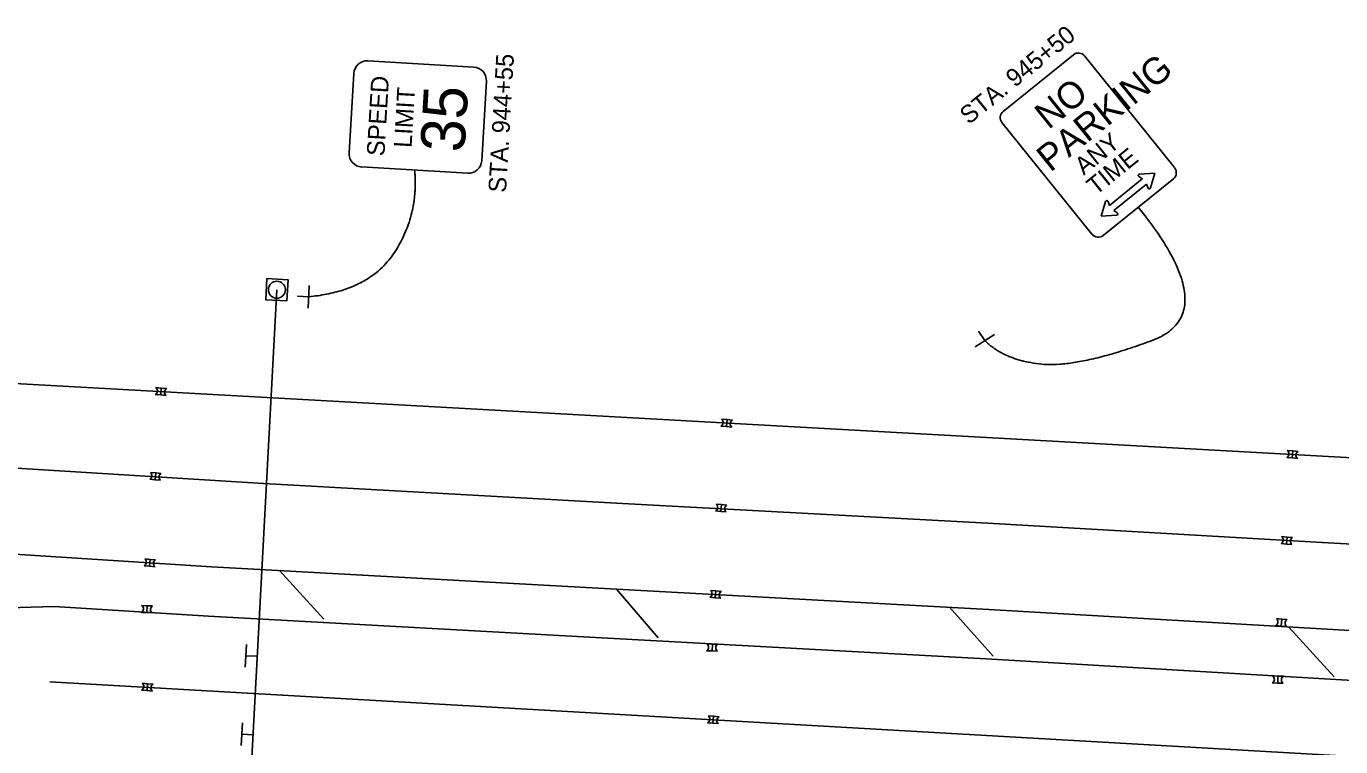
# Model space of a CAD drawing. Extents: x 1847379 to 1850904, y 217032 to 220169.
# Drawn here: x 1848555.2 to 1848740.8, y 218856.2 to 218957.9 of the extents above; entities that cross this region are included whole.
import ezdxf

# ---------------------------------------------------------------- set-up
doc = ezdxf.new("R2010")
doc.units = 0
for name, color, linetype in [('PM_P_Cells', 7, 'Continuous'), ('PM_P_CL_Double_Solid', 7, 'Continuous'), ('PM_P_Edge_Line', 7, 'Continuous'), ('PM_P_Lane_Line', 7, 'Continuous'), ('PM_P_Transverse_Line', 7, 'Continuous'), ('SG_P_Poles', 7, 'Continuous'), ('SN_P_Signs', 7, 'Continuous'), ('SN_X_Public', 7, 'Continuous')]:
    doc.layers.add(name, color=color, linetype=linetype)

msp = doc.modelspace()

# ---------------------------------------------------------------- linework, layer by layer
at = {"layer": 'PM_P_Cells'}
for p, q in [((1848574.25, 218906.8), (1848573.48, 218906.87)), ((1848573.48, 218906.87), (1848574.25, 218906.8)), ((1848574.16, 218905.83), (1848574.25, 218906.8)), ((1848574.25, 218906.8), (1848575.02, 218906.73)), ((1848573.39, 218905.9), (1848574.16, 218905.83)), ((1848573.39, 218905.9), (1848574.16, 218905.83)), ((1848574.16, 218905.83), (1848574.93, 218905.76)), ((1848654.13, 218902.35), (1848653.36, 218902.42)), ((1848653.36, 218902.42), (1848654.13, 218902.35)), ((1848653.27, 218901.45), (1848654.04, 218901.38)), ((1848653.27, 218901.45), (1848654.04, 218901.38)), ((1848654.04, 218901.38), (1848654.13, 218902.35)), ((1848654.04, 218901.38), (1848654.81, 218901.31)), ((1848654.13, 218902.35), (1848654.9, 218902.28)), ((1848733.16, 218897.02), (1848733.92, 218896.95)), ((1848733.16, 218897.02), (1848733.92, 218896.95)), ((1848734.01, 218897.93), (1848733.24, 218898)), ((1848733.24, 218898), (1848734.01, 218897.93)), ((1848733.92, 218896.95), (1848734.01, 218897.93)), ((1848733.92, 218896.95), (1848734.69, 218896.88)), ((1848734.01, 218897.93), (1848734.78, 218897.86)), ((1848572.62, 218893.93), (1848573.38, 218893.86)), ((1848572.62, 218893.93), (1848573.38, 218893.86)), ((1848573.47, 218894.83), (1848572.71, 218894.9)), ((1848572.71, 218894.9), (1848573.47, 218894.83)), ((1848573.38, 218893.86), (1848573.47, 218894.83)), ((1848573.38, 218893.86), (1848574.15, 218893.79)), ((1848573.47, 218894.83), (1848574.24, 218894.76)), ((1848652.5, 218889.46), (1848653.26, 218889.39)), ((1848652.5, 218889.46), (1848653.26, 218889.39)), ((1848653.35, 218890.36), (1848652.58, 218890.43)), ((1848652.58, 218890.43), (1848653.35, 218890.36)), ((1848653.26, 218889.39), (1848653.35, 218890.36)), ((1848653.26, 218889.39), (1848654.03, 218889.32)), ((1848653.35, 218890.36), (1848654.12, 218890.29)), ((1848733.22, 218885.77), (1848732.45, 218885.84)), ((1848732.45, 218885.84), (1848733.22, 218885.77)), ((1848733.13, 218884.79), (1848733.22, 218885.77)), ((1848733.22, 218885.77), (1848733.99, 218885.7)), ((1848732.37, 218884.86), (1848733.13, 218884.79)), ((1848732.37, 218884.86), (1848733.13, 218884.79)), ((1848733.13, 218884.79), (1848733.9, 218884.72)), ((1848572.68, 218882.63), (1848571.91, 218882.7)), ((1848571.91, 218882.7), (1848572.68, 218882.63)), ((1848572.59, 218881.66), (1848572.68, 218882.63)), ((1848572.68, 218882.63), (1848573.45, 218882.56)), ((1848571.82, 218881.73), (1848572.59, 218881.66)), ((1848571.82, 218881.73), (1848572.59, 218881.66)), ((1848572.59, 218881.66), (1848573.36, 218881.59)), ((1848652.56, 218878.18), (1848651.79, 218878.25)), ((1848651.79, 218878.25), (1848652.56, 218878.18)), ((1848651.7, 218877.28), (1848652.47, 218877.21)), ((1848651.7, 218877.28), (1848652.47, 218877.21)), ((1848652.47, 218877.21), (1848652.56, 218878.18)), ((1848652.47, 218877.21), (1848653.24, 218877.14)), ((1848652.56, 218878.18), (1848653.33, 218878.11)), ((1848571.43, 218875.14), (1848572.2, 218875.11)), ((1848571.43, 218875.14), (1848572.2, 218875.11)), ((1848572.24, 218876.09), (1848571.47, 218876.11)), ((1848571.47, 218876.11), (1848572.24, 218876.09)), ((1848572.2, 218875.11), (1848572.24, 218876.09)), ((1848572.2, 218875.11), (1848572.97, 218875.08)), ((1848572.24, 218876.09), (1848573.01, 218876.06)), ((1848731.61, 218873.29), (1848732.38, 218873.22)), ((1848731.61, 218873.29), (1848732.38, 218873.22)), ((1848732.47, 218874.19), (1848731.7, 218874.26)), ((1848731.7, 218874.26), (1848732.47, 218874.19)), ((1848732.38, 218873.22), (1848732.47, 218874.19)), ((1848732.38, 218873.22), (1848733.15, 218873.15)), ((1848732.47, 218874.19), (1848733.24, 218874.13)), ((1848651.25, 218869.73), (1848652.02, 218869.71)), ((1848651.25, 218869.73), (1848652.02, 218869.71)), ((1848652.06, 218870.68), (1848651.29, 218870.71)), ((1848651.29, 218870.71), (1848652.06, 218870.68)), ((1848652.02, 218869.71), (1848652.06, 218870.68)), ((1848652.02, 218869.71), (1848652.79, 218869.68)), ((1848652.06, 218870.68), (1848652.83, 218870.66)), ((1848731.93, 218866.15), (1848731.16, 218866.18)), ((1848731.16, 218866.18), (1848731.93, 218866.15)), ((1848731.9, 218865.17), (1848731.93, 218866.15)), ((1848731.93, 218866.15), (1848732.7, 218866.12)), ((1848571.46, 218864.17), (1848572.23, 218864.1)), ((1848571.46, 218864.17), (1848572.23, 218864.1)), ((1848572.32, 218865.08), (1848571.55, 218865.15)), ((1848571.55, 218865.15), (1848572.32, 218865.08)), ((1848572.23, 218864.1), (1848572.32, 218865.08)), ((1848572.23, 218864.1), (1848573, 218864.04)), ((1848572.32, 218865.08), (1848573.09, 218865.01)), ((1848731.13, 218865.2), (1848731.9, 218865.17)), ((1848731.13, 218865.2), (1848731.9, 218865.17)), ((1848731.9, 218865.17), (1848732.67, 218865.14)), ((1848652.23, 218860.48), (1848651.47, 218860.55)), ((1848651.47, 218860.55), (1848652.23, 218860.48)), ((1848652.15, 218859.5), (1848652.23, 218860.48)), ((1848652.23, 218860.48), (1848653, 218860.41)), ((1848651.38, 218859.57), (1848652.15, 218859.5)), ((1848651.38, 218859.57), (1848652.15, 218859.5)), ((1848652.15, 218859.5), (1848652.91, 218859.44))]:
    msp.add_line(p, q, dxfattribs=at)
for centre, start, end in [((1848573.13, 218906.41), 296.8063, 52.8586), ((1848573.13, 218906.41), 296.8063, 52.8586), ((1848575.28, 218906.22), 116.8063, 232.8586), ((1848653.01, 218901.96), 296.8063, 52.8586), ((1848653.01, 218901.96), 296.8063, 52.8586), ((1848655.16, 218901.77), 116.8063, 232.8586), ((1848732.9, 218897.54), 296.8063, 52.8586), ((1848732.9, 218897.54), 296.8063, 52.8586), ((1848735.04, 218897.34), 116.8063, 232.8586), ((1848572.36, 218894.44), 296.8063, 52.8586), ((1848572.36, 218894.44), 296.8063, 52.8586), ((1848574.5, 218894.25), 116.8063, 232.8586), ((1848652.24, 218889.97), 296.8063, 52.8586), ((1848652.24, 218889.97), 296.8063, 52.8586), ((1848654.38, 218889.78), 116.8063, 232.8586), ((1848732.11, 218885.38), 296.8063, 52.8586), ((1848732.11, 218885.38), 296.8063, 52.8586), ((1848734.25, 218885.18), 116.8063, 232.8586), ((1848571.56, 218882.24), 296.8063, 52.8586), ((1848571.56, 218882.24), 296.8063, 52.8586), ((1848573.71, 218882.05), 116.8063, 232.8586), ((1848651.44, 218877.79), 296.8063, 52.8586), ((1848651.44, 218877.79), 296.8063, 52.8586), ((1848653.59, 218877.6), 116.8063, 232.8586), ((1848571.15, 218875.64), 299.9028, 55.9551), ((1848571.15, 218875.64), 299.9028, 55.9551), ((1848573.3, 218875.56), 119.9028, 235.9551), ((1848731.35, 218873.81), 296.8063, 52.8586), ((1848731.35, 218873.81), 296.8063, 52.8586), ((1848733.5, 218873.61), 116.8063, 232.8586), ((1848650.96, 218870.23), 299.9028, 55.9551), ((1848650.96, 218870.23), 299.9028, 55.9551), ((1848653.11, 218870.16), 119.9028, 235.9551), ((1848730.84, 218865.7), 299.9028, 55.9551), ((1848730.84, 218865.7), 299.9028, 55.9551), ((1848732.99, 218865.62), 119.9028, 235.9551), ((1848571.2, 218864.69), 296.8063, 52.8586), ((1848571.2, 218864.69), 296.8063, 52.8586), ((1848573.35, 218864.49), 116.8063, 232.8586), ((1848651.12, 218860.09), 296.8063, 52.8586), ((1848651.12, 218860.09), 296.8063, 52.8586), ((1848653.26, 218859.89), 116.8063, 232.8586)]:
    msp.add_arc(centre, 0.576, start, end, dxfattribs=at)
at = {"layer": 'PM_P_CL_Double_Solid'}
msp.add_line((1848494.98, 218874.17), (1848559.13, 218875.98), dxfattribs=at)
for points in [[(1848092.4, 218893.94), (1848142.1, 218891.52), (1848192.74, 218889.17), (1848244.1, 218886.91), (1848292.7, 218884.63), (1848342.36, 218882.33), (1848384.68, 218880.9), (1848410.72, 218884.71), (1848435.62, 218888.6), (1848446.29, 218889.11), (1848496.28, 218886.67), (1848532.23, 218884.71), (1848581.34, 218881.58), (1848635.08, 218878.63), (1848691.11, 218875.57), (1848742.91, 218872.53), (1848797.97, 218869.41), (1848838.45, 218867.24), (1848839.96, 218866.49), (1848840.79, 218865.04), (1848840.57, 218862.3), (1848839.59, 218860.87), (1848837.82, 218860.26)], [(1848559.13, 218875.98), (1848580.93, 218874.59), (1848634.7, 218871.64), (1848690.71, 218868.59), (1848742.51, 218865.54), (1848797.58, 218862.42), (1848837.82, 218860.26)]]:
    msp.add_lwpolyline(points, dxfattribs=at)
at = {"layer": 'PM_P_Edge_Line'}
msp.add_line((1848468.87, 218912.17), (1848839.16, 218891.61), dxfattribs=at)
at = {"layer": 'PM_P_Lane_Line'}
msp.add_line((1848558.52, 218865.36), (1848836.12, 218849.43), dxfattribs=at)
msp.add_lwpolyline([(1848093.91, 218917.13), (1848143.09, 218915.12), (1848190.28, 218912.91), (1848241.04, 218910.6), (1848292.87, 218908.29), (1848342.88, 218905.97), (1848396.54, 218903.43), (1848443.56, 218901.44), (1848492.82, 218898.95), (1848543.12, 218896.17), (1848588.69, 218893.34), (1848639.37, 218890.51), (1848690.94, 218887.73), (1848738.16, 218885.02), (1848789.62, 218882.19), (1848826.41, 218879.84)], dxfattribs=at)
at = {"layer": 'PM_P_Transverse_Line'}
for p, q in [((1848597.19, 218874.18), (1848590.95, 218881.05)), ((1848644.43, 218871.55), (1848638.52, 218878.44)), ((1848691.7, 218868.95), (1848685.53, 218875.88)), ((1848739.85, 218866.04), (1848733.47, 218873.08))]:
    msp.add_line(p, q, dxfattribs=at)
at = {"layer": 'SG_P_Poles'}
msp.add_lwpolyline([(1848591.99, 218919.11), (1848592.15, 218922.1), (1848589.15, 218922.26), (1848588.99, 218919.27)], close=True, dxfattribs=at)
msp.add_circle((1848590.57, 218920.69), 1.2, dxfattribs=at)
at = {"layer": 'SN_P_Signs'}
for p, q in [((1848584.68, 218810.84), (1848590.57, 218920.69)), ((1848586.11, 218867.43), (1848586.28, 218870.63)), ((1848586.2, 218869.03), (1848587.8, 218868.95)), ((1848585.52, 218856.36), (1848585.69, 218859.56)), ((1848585.61, 218857.96), (1848587.2, 218857.88))]:
    msp.add_line(p, q, dxfattribs=at)
at = {"layer": 'SN_X_Public'}
for p, q in [((1848712.77, 218936.32), (1848708.14, 218932.59)), ((1848712.28, 218936.65), (1848712.78, 218936.32)), ((1848714.53, 218937.13), (1848712.37, 218936.99)), ((1848712.78, 218936.32), (1848712.77, 218936.32)), ((1848713.93, 218935.05), (1848714.53, 218937.13)), ((1848710.75, 218934.09), (1848710.75, 218934.09)), ((1848713.37, 218935.59), (1848713.58, 218935.04)), ((1848707.58, 218933.13), (1848706.98, 218931.05)), ((1848708.14, 218932.59), (1848707.93, 218933.15)), ((1848708.14, 218932.59), (1848708.15, 218932.59)), ((1848706.98, 218931.05), (1848709.14, 218931.2)), ((1848709.23, 218931.53), (1848708.73, 218931.86)), ((1848595.15, 218921.29), (1848594.99, 218918.09)), ((1848595.07, 218919.69), (1848593.47, 218919.77)), ((1848691.88, 218914.38), (1848689.19, 218912.63)), ((1848690.53, 218913.51), (1848689.66, 218914.85))]:
    msp.add_line(p, q, dxfattribs=at)
for points in [[(1848618.38, 218952.11), (1848603.41, 218952.98)], [(1848703.05, 218953.86), (1848693.12, 218945.85)], [(1848717.34, 218937.92), (1848704.63, 218953.69)], [(1848601.43, 218951.22), (1848600.77, 218939.99)], [(1848619.49, 218938.9), (1848620.15, 218950.13)], [(1848692.95, 218944.27), (1848705.66, 218928.51)], [(1848602.54, 218938.01), (1848617.51, 218937.14)], [(1848707.24, 218928.34), (1848717.17, 218936.34)], [(1848708.73, 218931.86), (1848713.36, 218935.59)]]:
    msp.add_lwpolyline(points, dxfattribs=at)
for centre, radius, start, end in [((1848603.3, 218951.11), 1.88, 86.6669, 176.6669), ((1848703.76, 218952.98), 1.12, 38.8676, 128.8676), ((1848618.27, 218950.24), 1.88, 356.6669, 86.6669), ((1848693.83, 218944.98), 1.12, 128.8676, 218.8676), ((1848602.65, 218939.88), 1.88, 176.6669, 266.6669), ((1848617.62, 218939.01), 1.88, 266.6669, 356.6669), ((1848716.46, 218937.21), 1.12, 308.8676, 38.8676), ((1848712.38, 218936.81), 0.182, 93.7884, 236.5054), ((1848713.75, 218935.1), 0.182, 201.2298, 343.9469), ((1848707.76, 218933.08), 0.182, 21.2298, 163.9469), ((1848709.13, 218931.38), 0.182, 273.7884, 56.5054), ((1848706.54, 218929.21), 1.12, 218.8676, 308.8676)]:
    msp.add_arc(centre, radius, start, end, dxfattribs=at)
for points in [[(1848595.07, 218919.69), (1848603.6, 218920.53), (1848610.62, 218931.17), (1848610.02, 218937.57)], [(1848690.53, 218913.51), (1848693.38, 218910.68), (1848703.79, 218909.69), (1848724.38, 218917.29), (1848712.2, 218932.34)]]:
    msp.add_open_spline(points, degree=2, dxfattribs=at)

# ---------------------------------------------------------------- texts
for s, height, rotation, p in [('STA. 945+50', 2.5, 38.8676, (1848688.27, 218943.91)), ('STA. 944+55', 2.5, 86.6669, (1848622.92, 218934.34)), ('PARKING', 3.75, 38.8676, (1848699.79, 218937.18)), ('SPEED', 2.5, 86.6669, (1848605.75, 218939.49)), ('LIMIT', 2.5, 86.6669, (1848609.58, 218940.67)), ('35', 6.25, 86.6669, (1848617.05, 218939.99)), ('NO', 3.75, 38.8676, (1848699.53, 218943.2)), ('ANY', 2.5, 38.8676, (1848704.5, 218936.76)), ('TIME', 2.5, 38.8676, (1848706.21, 218933.93))]:
    msp.add_text(s, height=height, rotation=rotation, dxfattribs=at).set_placement(p)

doc.saveas('drawing.dxf')
